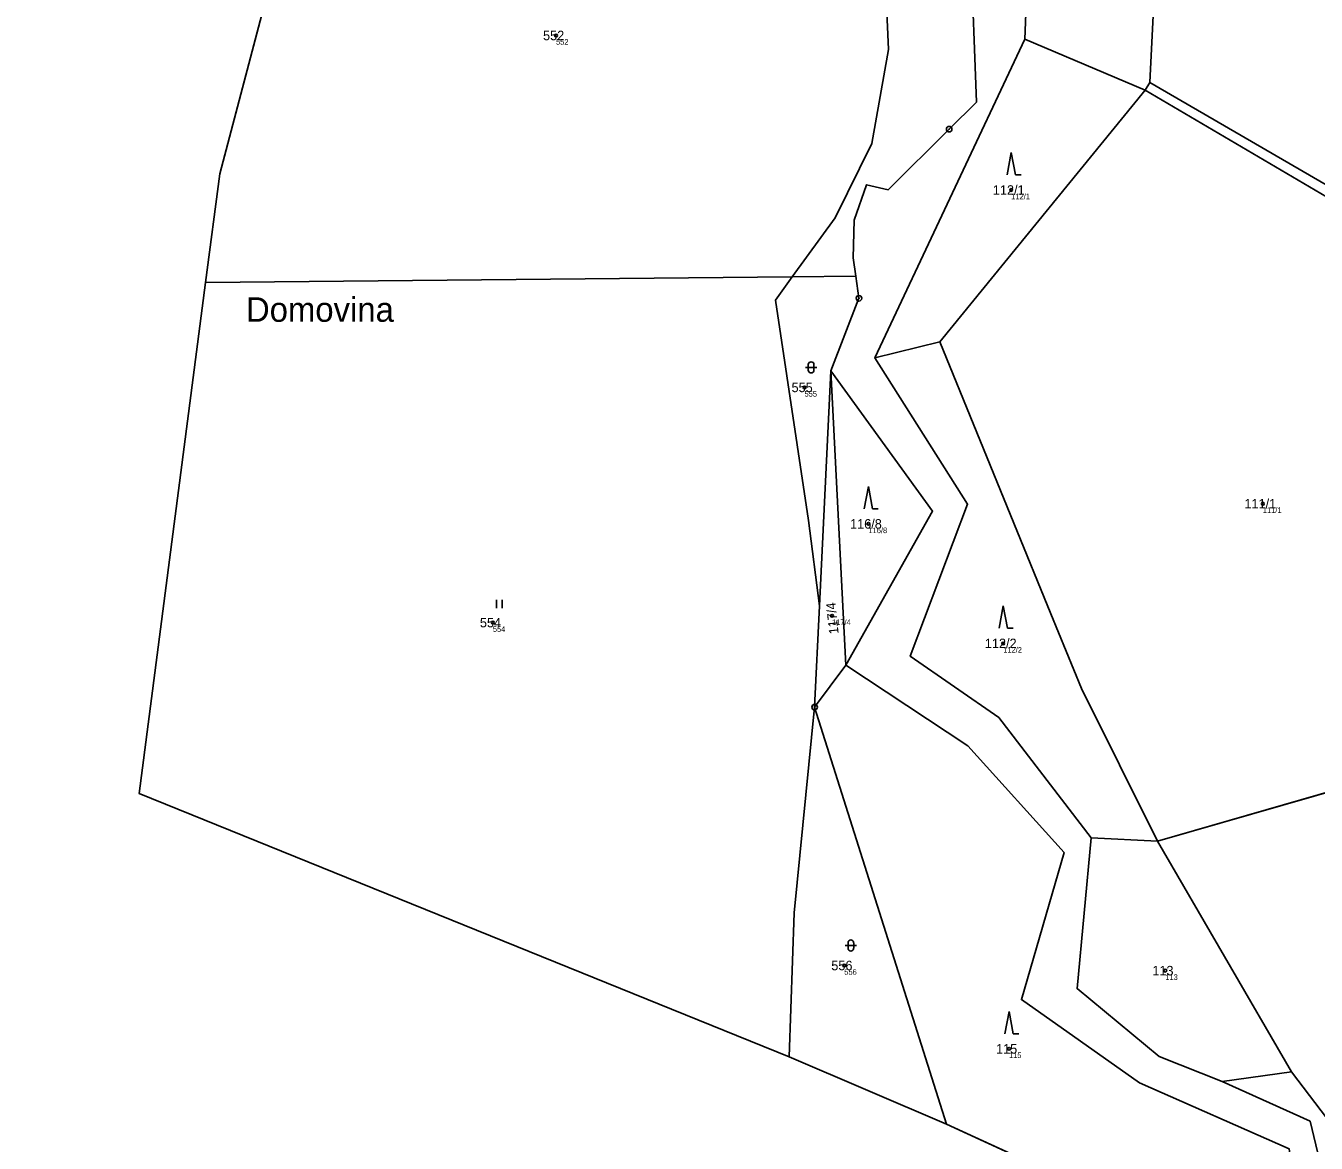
# Model space of a CAD drawing. Extents: x -700238 to -698499, y -1070626 to -1068006.
# Drawn here: x -700206.2 to -699975.1, y -1069308.9 to -1069108.8 of the extents above; entities that cross this region are included whole.
import ezdxf

# ---------------------------------------------------------------- set-up
doc = ezdxf.new("R2010")
doc.units = 0
for name, color, linetype in [('Definiční body', 7, 'Continuous'), ('Hranice parcel', 7, 'Continuous'), ('Parcelní čísla', 7, 'Continuous'), ('Polygon ku', 7, 'Continuous'), ('Polygon parcely', 7, 'Continuous'), ('Pop  PČ popisy', 7, 'Continuous'), ('Značky bodu BP', 7, 'Continuous'), ('Značky kultur', 7, 'Continuous')]:
    doc.layers.add(name, color=color, linetype=linetype)

msp = doc.modelspace()

# ---------------------------------------------------------------- linework, layer by layer
at = {"layer": 'Definiční body'}
for centre in [(-700111.27, -1069110.53994), (-700029.75, -1069138.20994), (-700066.77, -1069173.55994), (-699984.69, -1069194.37994), (-700055.32, -1069197.99994), (-700122.58, -1069215.67994), (-700061.84, -1069214.45994), (-700031.18, -1069219.39994), (-700059.65, -1069277.07994), (-700002.16, -1069277.99994), (-700030.15, -1069291.99994)]:
    msp.add_circle(centre, 0.25, dxfattribs=at)
at = {"layer": 'Hranice parcel'}
for p, q in [((-700157.89, -1069083.6), (-700171.46, -1069135.31)), ((-700027.33, -1069111.21), (-700054.16, -1069168.28)), ((-700005.74, -1069120.31), (-700027.33, -1069111.21)), ((-700005.74, -1069120.31), (-700042.54, -1069165.4)), ((-700004.92, -1069118.95), (-700005.74, -1069120.31)), ((-700171.46, -1069135.31), (-700174.05, -1069154.77)), ((-700174.05, -1069154.77), (-700185.93, -1069246.25)), ((-700068.97, -1069153.77), (-700174.05, -1069154.77)), ((-700068.97, -1069153.77), (-700057.59, -1069153.66)), ((-700054.16, -1069168.28), (-700042.54, -1069165.4)), ((-700062.03, -1069170.6), (-700064.08, -1069212.69)), ((-700062.03, -1069170.6), (-700059.38, -1069223.3)), ((-700064.08, -1069212.69), (-700064.96, -1069230.83)), ((-700059.38, -1069223.3), (-700064.96, -1069230.83)), ((-700064.96, -1069230.83), (-700041.36, -1069305.51)), ((-700003.55, -1069254.82), (-699926.54, -1069232.62)), ((-700185.93, -1069246.25), (-700069.54, -1069293.44)), ((-700015.45, -1069254.19), (-700003.55, -1069254.82)), ((-699979.58, -1069296.13), (-700003.55, -1069254.82)), ((-700069.54, -1069293.44), (-700041.36, -1069305.51)), ((-699991.98, -1069297.84), (-699979.58, -1069296.13)), ((-699970.06, -1069308.6), (-699979.58, -1069296.13)), ((-700041.36, -1069305.51), (-700005.92, -1069321.74))]:
    msp.add_line(p, q, dxfattribs=at)
for points in [[(-700027.33, -1069111.21), (-700026.63, -1069092.7), (-700034.7, -1069076.66), (-700049.69, -1069082.4), (-700062.86, -1069066.12), (-700062.68, -1069050.83), (-700070.99, -1069037.66), (-700097.4, -1069023.81), (-700096.33, -1069006.23), (-700081.63, -1068991.35)], [(-700034.9, -1069033.46), (-700014.52, -1069069.43), (-700003.97, -1069099.76), (-700004.92, -1069118.95)], [(-700085.37, -1069037.36), (-700081.17, -1069039.9), (-700073.99, -1069053.06), (-700071.62, -1069062.77), (-700054, -1069088.93), (-700039.82, -1069084.64), (-700036.97, -1069095.58), (-700035.98, -1069122.48), (-700040.87, -1069127.32), (-700051.79, -1069138.15), (-700055.65, -1069137.28), (-700057.91, -1069143.63), (-700058.06, -1069150.36), (-700057.59, -1069153.66)], [(-700089.28, -1069042.77), (-700080.34, -1069056.58), (-700052.16, -1069103.61), (-700051.73, -1069113.03), (-700054.71, -1069129.86), (-700061.3, -1069143.2), (-700068.97, -1069153.77)], [(-700005.74, -1069120.31), (-699946.89, -1069154.93), (-699902.29, -1069182.28)], [(-699887.09, -1069189.8), (-699942.21, -1069155.36), (-700004.92, -1069118.95)], [(-700064.08, -1069212.69), (-700066.04, -1069197.38), (-700071.96, -1069157.92), (-700068.97, -1069153.77)], [(-700057.59, -1069153.66), (-700057.03, -1069157.6), (-700062.03, -1069170.6)], [(-700042.54, -1069165.4), (-700022.67, -1069214.1), (-700017.18, -1069227.45), (-700003.55, -1069254.82)], [(-700054.16, -1069168.28), (-700037.56, -1069194.48), (-700047.83, -1069221.71), (-700031.95, -1069232.67), (-700015.45, -1069254.19)], [(-700059.38, -1069223.3), (-700043.84, -1069195.7), (-700062.03, -1069170.6)], [(-699956.99, -1069358.26), (-699975.79, -1069335.05), (-699979.99, -1069309.89), (-700006.78, -1069298.08), (-700027.93, -1069283.18), (-700020.28, -1069256.86), (-700037.53, -1069237.76), (-700059.38, -1069223.3)], [(-700069.54, -1069293.44), (-700068.61, -1069267.65), (-700064.96, -1069230.83)], [(-700015.45, -1069254.19), (-700017.96, -1069281.2), (-700003.25, -1069293.37), (-699991.98, -1069297.84)], [(-699991.98, -1069297.84), (-699976.24, -1069304.98), (-699969.55, -1069332.87), (-699957.94, -1069346.12)]]:
    msp.add_lwpolyline(points, dxfattribs=at)
at = {"layer": 'Polygon ku'}
msp.add_lwpolyline([(-700202.74, -1068906.65), (-700206.22, -1068936.25), (-700204.79, -1068958.38), (-700199.47, -1068994.48), (-700196.14, -1069017.11), (-700172.11, -1069050.54), (-700165.2, -1069063.61), (-700160.12, -1069077.18), (-700157.89, -1069083.6), (-700171.46, -1069135.31), (-700174.05, -1069154.77), (-700185.93, -1069246.25), (-700069.54, -1069293.44), (-700041.36, -1069305.51), (-700005.92, -1069321.74)], dxfattribs=at)
at = {"layer": 'Polygon parcely'}
for points in [[(-699927.83, -1068963.6), (-699966.54, -1068943.51), (-700010.84, -1068923.12), (-700020.68, -1068980.4), (-700045.28, -1068979.92), (-700043.09, -1068995.75), (-700040.74, -1069016.45), (-700034.9, -1069033.46), (-700014.52, -1069069.43), (-700003.97, -1069099.76), (-700004.92, -1069118.95), (-699942.21, -1069155.36), (-699887.09, -1069189.8), (-699876.74, -1069160.5), (-699858.28, -1069127.86), (-699826.38, -1069090.56), (-699861.15, -1069061.15), (-699908.65, -1069027.8), (-699886.24, -1068990.68)], [(-700081.63, -1068991.35), (-700096.33, -1069006.23), (-700097.4, -1069023.81), (-700070.99, -1069037.66), (-700062.68, -1069050.83), (-700062.86, -1069066.12), (-700049.69, -1069082.4), (-700034.7, -1069076.66), (-700026.63, -1069092.7), (-700027.33, -1069111.21), (-700005.74, -1069120.31), (-700004.92, -1069118.95), (-700003.97, -1069099.76), (-700014.52, -1069069.43), (-700034.9, -1069033.46), (-700045.81, -1069016.33)], [(-700061.3, -1069143.2), (-700068.97, -1069153.77), (-700057.59, -1069153.66), (-700058.06, -1069150.36), (-700057.91, -1069143.63), (-700055.65, -1069137.28), (-700051.79, -1069138.15), (-700040.87, -1069127.32), (-700035.98, -1069122.48), (-700036.97, -1069095.58), (-700039.82, -1069084.64), (-700054, -1069088.93), (-700071.62, -1069062.77), (-700073.99, -1069053.06), (-700081.17, -1069039.9), (-700085.37, -1069037.36), (-700089.28, -1069042.77), (-700080.34, -1069056.58), (-700052.16, -1069103.61), (-700051.73, -1069113.03), (-700054.71, -1069129.86)], [(-700174.05, -1069154.77), (-700068.97, -1069153.77), (-700061.3, -1069143.2), (-700054.71, -1069129.86), (-700051.73, -1069113.03), (-700052.16, -1069103.61), (-700080.34, -1069056.58), (-700089.28, -1069042.77), (-700157.89, -1069083.6), (-700171.46, -1069135.31)], [(-700027.33, -1069111.21), (-700054.16, -1069168.28), (-700042.54, -1069165.4), (-700005.74, -1069120.31)], [(-699930.82, -1069226.53), (-699939.28, -1069214.5), (-699916.53, -1069194.74), (-699905.13, -1069184.8), (-699902.29, -1069182.28), (-699946.89, -1069154.93), (-700005.74, -1069120.31), (-700042.54, -1069165.4), (-700022.67, -1069214.1), (-700017.18, -1069227.45), (-700003.55, -1069254.82), (-699926.54, -1069232.62)], [(-699887.66, -1069191.91), (-699887.09, -1069189.8), (-699942.21, -1069155.36), (-700004.92, -1069118.95), (-700005.74, -1069120.31), (-699946.89, -1069154.93), (-699902.29, -1069182.28)], [(-700185.93, -1069246.25), (-700069.54, -1069293.44), (-700068.61, -1069267.65), (-700064.96, -1069230.83), (-700064.08, -1069212.69), (-700066.04, -1069197.38), (-700071.96, -1069157.92), (-700068.97, -1069153.77), (-700174.05, -1069154.77)], [(-700057.59, -1069153.66), (-700068.97, -1069153.77), (-700071.96, -1069157.92), (-700066.04, -1069197.38), (-700064.08, -1069212.69), (-700062.03, -1069170.6), (-700057.03, -1069157.6)], [(-700015.45, -1069254.19), (-700003.55, -1069254.82), (-700017.18, -1069227.45), (-700022.67, -1069214.1), (-700042.54, -1069165.4), (-700054.16, -1069168.28), (-700037.56, -1069194.48), (-700047.83, -1069221.71), (-700031.95, -1069232.67)], [(-700064.08, -1069212.69), (-700064.96, -1069230.83), (-700059.38, -1069223.3), (-700062.03, -1069170.6)], [(-700062.03, -1069170.6), (-700059.38, -1069223.3), (-700043.84, -1069195.7)], [(-700002.95, -1069324.2), (-699967.55, -1069360.91), (-699962.27, -1069361.52), (-699956.99, -1069358.26), (-699975.79, -1069335.05), (-699979.99, -1069309.89), (-700006.78, -1069298.08), (-700027.93, -1069283.18), (-700020.28, -1069256.86), (-700037.53, -1069237.76), (-700059.38, -1069223.3), (-700064.96, -1069230.83), (-700041.36, -1069305.51), (-700005.92, -1069321.74)], [(-700041.36, -1069305.51), (-700064.96, -1069230.83), (-700068.61, -1069267.65), (-700069.54, -1069293.44)], [(-699914.55, -1069282.08), (-699915.87, -1069262.75), (-699916.42, -1069252.1), (-699921.68, -1069239.53), (-699926.54, -1069232.62), (-700003.55, -1069254.82), (-699979.58, -1069296.13), (-699970.06, -1069308.6), (-699947.36, -1069300.71), (-699921.46, -1069291.8), (-699913.95, -1069294.7)], [(-700017.96, -1069281.2), (-700003.25, -1069293.37), (-699991.98, -1069297.84), (-699979.58, -1069296.13), (-700003.55, -1069254.82), (-700015.45, -1069254.19)], [(-699969.55, -1069332.87), (-699957.94, -1069346.12), (-699947.81, -1069346.98), (-699935.09, -1069337.33), (-699928.45, -1069336.63), (-699927.65, -1069333.4), (-699935.74, -1069333.78), (-699955.02, -1069331.3), (-699964.08, -1069317.15), (-699970.06, -1069308.6), (-699979.58, -1069296.13), (-699991.98, -1069297.84), (-699976.24, -1069304.98)]]:
    msp.add_lwpolyline(points, close=True, dxfattribs=at)
for points in [[(-699969.55, -1069332.87), (-699976.24, -1069304.98), (-699991.98, -1069297.84), (-700003.25, -1069293.37), (-700017.96, -1069281.2), (-700015.45, -1069254.19), (-700031.95, -1069232.67), (-700047.83, -1069221.71), (-700037.56, -1069194.48), (-700054.16, -1069168.28), (-700027.33, -1069111.21), (-700026.63, -1069092.7), (-700034.7, -1069076.66), (-700049.69, -1069082.4), (-700062.86, -1069066.12), (-700062.68, -1069050.83), (-700070.99, -1069037.66), (-700097.4, -1069023.81), (-700096.33, -1069006.23), (-700081.63, -1068991.35), (-700077.69, -1068973.77)], [(-700036.97, -1069095.58), (-700035.98, -1069122.48), (-700040.87, -1069127.32), (-700051.79, -1069138.15), (-700055.65, -1069137.28), (-700057.91, -1069143.63), (-700058.06, -1069150.36), (-700057.59, -1069153.66), (-700057.03, -1069157.6), (-700062.03, -1069170.6), (-700043.84, -1069195.7), (-700059.38, -1069223.3), (-700037.53, -1069237.76), (-700020.28, -1069256.86), (-700027.93, -1069283.18), (-700006.78, -1069298.08), (-699979.99, -1069309.89)]]:
    msp.add_lwpolyline(points, dxfattribs=at)
at = {"layer": 'Značky bodu BP'}
for centre, radius in [((-700040.87, -1069127.31988), 0.5), ((-700040.87, -1069127.31988), 0.0303), ((-700057.03, -1069157.59988), 0.5), ((-700057.03, -1069157.59988), 0.0303), ((-700064.96, -1069230.82988), 0.5), ((-700064.96, -1069230.82988), 0.0303)]:
    msp.add_circle(centre, radius, dxfattribs=at)
at = {"layer": 'Značky kultur'}
for p, q in [((-700029.75, -1069131.51), (-700030.5, -1069135.51)), ((-700029, -1069135.51), (-700029.75, -1069131.51)), ((-700029, -1069135.51), (-700028.004, -1069135.51)), ((-700066.091, -1069169.471), (-700066.091, -1069170.472)), ((-700065.089, -1069170.472), (-700065.089, -1069169.471)), ((-700066.591, -1069169.971), (-700064.589, -1069169.971)), ((-700055.32, -1069191.3), (-700056.07, -1069195.3)), ((-700054.57, -1069195.3), (-700055.32, -1069191.3)), ((-700054.57, -1069195.3), (-700053.574, -1069195.3)), ((-700121.921, -1069213.09), (-700121.921, -1069211.59)), ((-700120.92, -1069213.09), (-700120.92, -1069211.59)), ((-700031.18, -1069212.7), (-700031.93, -1069216.7)), ((-700030.43, -1069216.7), (-700031.18, -1069212.7)), ((-700030.43, -1069216.7), (-700029.434, -1069216.7)), ((-700058.971, -1069272.991), (-700058.971, -1069273.992)), ((-700057.969, -1069273.992), (-700057.969, -1069272.991)), ((-700059.471, -1069273.491), (-700057.469, -1069273.491)), ((-700030.15, -1069285.3), (-700030.9, -1069289.3)), ((-700029.4, -1069289.3), (-700030.15, -1069285.3)), ((-700029.4, -1069289.3), (-700028.404, -1069289.3))]:
    msp.add_line(p, q, dxfattribs=at)
for centre, start, end in [((-700065.59, -1069169.4709), 0, 180), ((-700065.59, -1069170.4709), 180, 359.9878861), ((-700058.47, -1069272.9909), 0, 180), ((-700058.47, -1069273.9909), 180, 359.9878861)]:
    msp.add_arc(centre, 0.5, start, end, dxfattribs=at)

# ---------------------------------------------------------------- texts
at = {"layer": 'Definiční body'}
for s, p in [('552', (-700111.27, -1069112.196)), ('112/1', (-700029.75, -1069139.866)), ('555', (-700066.77, -1069175.216)), ('111/1', (-699984.69, -1069196.036)), ('116/8', (-700055.32, -1069199.656)), ('117/4', (-700061.84, -1069216.116)), ('554', (-700122.58, -1069217.336)), ('112/2', (-700031.18, -1069221.056)), ('556', (-700059.65, -1069278.736)), ('113', (-700002.16, -1069279.656)), ('115', (-700030.15, -1069293.656))]:
    msp.add_text(s, height=0.999996, dxfattribs=at).set_placement(p)
at = {"layer": 'Parcelní čísla'}
for s, p in [('552', (-700113.595, -1069111.39)), ('112/1', (-700033.048, -1069139.06)), ('555', (-700069.095, -1069174.41)), ('111/1', (-699987.988, -1069195.229)), ('116/8', (-700058.618, -1069198.85)), ('554', (-700124.905, -1069216.529)), ('112/2', (-700034.478, -1069220.249)), ('556', (-700061.975, -1069277.93)), ('113', (-700004.485, -1069278.85)), ('115', (-700032.475, -1069292.85))]:
    msp.add_text(s, height=1.699998, dxfattribs=at).set_placement(p)
msp.add_text('117/4', height=1.699998, rotation=96, dxfattribs=at).set_placement((-700060.649, -1069217.651))
at = {"layer": 'Pop  PČ popisy'}
msp.add_text('Domovina', height=4.399998, dxfattribs=at).set_placement((-700166.796, -1069161.81))

doc.saveas('drawing.dxf')
